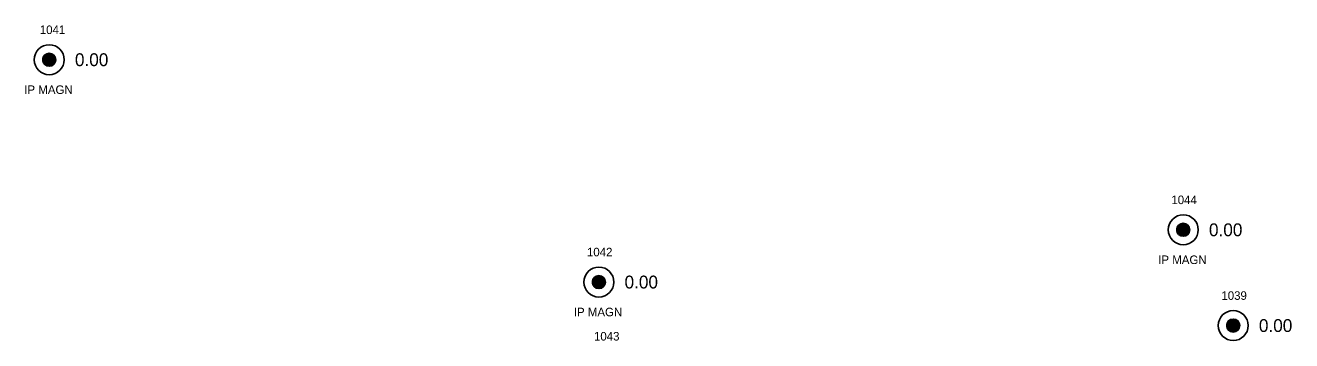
# Model space of a CAD drawing. Extents: x 1539151 to 1541799, y 1198646 to 1201165.
# Drawn here: x 1539955.6 to 1540103.4, y 1199874.2 to 1199911 of the extents above; entities that cross this region are included whole.
import ezdxf

# ---------------------------------------------------------------- set-up
doc = ezdxf.new("R2010")
doc.units = 0
for name, color, linetype in [('RD_EX_DV_Prop_txCode', 7, 'Continuous'), ('RD_EX_DV_PropPin', 7, 'Continuous'), ('RD_EX_TX_DV_Prop_ELEV', 7, 'Continuous'), ('RD_SMD_Locator', 7, 'Continuous')]:
    doc.layers.add(name, color=color, linetype=linetype)

msp = doc.modelspace()

# ---------------------------------------------------------------- linework, layer by layer
at = {"layer": 'RD_EX_DV_PropPin'}
for p, q in [((1539957.97, 1199906.34), (1539957.97, 1199907.66)), ((1539958.01, 1199906.32), (1539958.01, 1199907.67)), ((1539958.04, 1199906.31), (1539958.04, 1199907.69)), ((1539958.08, 1199906.29), (1539958.08, 1199907.71)), ((1539958.11, 1199906.28), (1539958.11, 1199907.72)), ((1539958.15, 1199906.27), (1539958.15, 1199907.73)), ((1539958.18, 1199906.26), (1539958.18, 1199907.74)), ((1539958.22, 1199906.25), (1539958.22, 1199907.75)), ((1539958.25, 1199906.25), (1539958.25, 1199907.75)), ((1539958.29, 1199906.24), (1539958.29, 1199907.76)), ((1539958.32, 1199906.24), (1539958.32, 1199907.76)), ((1539958.36, 1199906.24), (1539958.36, 1199907.76)), ((1539958.39, 1199906.24), (1539958.39, 1199907.76)), ((1539958.43, 1199906.24), (1539958.43, 1199907.76)), ((1539958.46, 1199906.25), (1539958.46, 1199907.75)), ((1539958.5, 1199906.25), (1539958.5, 1199907.75)), ((1539958.53, 1199906.26), (1539958.53, 1199907.74)), ((1539958.57, 1199906.27), (1539958.57, 1199907.73)), ((1539958.6, 1199906.28), (1539958.6, 1199907.72)), ((1539958.64, 1199906.29), (1539958.64, 1199907.71)), ((1539958.67, 1199906.31), (1539958.67, 1199907.69)), ((1539958.71, 1199906.32), (1539958.71, 1199907.67)), ((1539958.74, 1199906.34), (1539958.74, 1199907.66)), ((1539957.62, 1199906.8), (1539957.62, 1199907.2)), ((1539957.66, 1199906.7), (1539957.66, 1199907.3)), ((1539957.69, 1199906.63), (1539957.69, 1199907.37)), ((1539957.73, 1199906.57), (1539957.73, 1199907.43)), ((1539957.76, 1199906.53), (1539957.76, 1199907.47)), ((1539957.8, 1199906.48), (1539957.8, 1199907.51)), ((1539957.83, 1199906.45), (1539957.83, 1199907.55)), ((1539957.87, 1199906.42), (1539957.87, 1199907.58)), ((1539957.9, 1199906.39), (1539957.9, 1199907.61)), ((1539957.94, 1199906.36), (1539957.94, 1199907.63)), ((1539958.78, 1199906.36), (1539958.78, 1199907.63)), ((1539958.81, 1199906.39), (1539958.81, 1199907.61)), ((1539958.85, 1199906.42), (1539958.85, 1199907.58)), ((1539958.88, 1199906.45), (1539958.88, 1199907.55)), ((1539958.92, 1199906.48), (1539958.92, 1199907.51)), ((1539958.95, 1199906.53), (1539958.95, 1199907.47)), ((1539958.99, 1199906.57), (1539958.99, 1199907.43)), ((1539959.02, 1199906.63), (1539959.02, 1199907.37)), ((1539959.06, 1199906.7), (1539959.06, 1199907.3)), ((1539959.09, 1199906.8), (1539959.09, 1199907.2)), ((1540090.04, 1199886.94), (1540090.04, 1199887.33)), ((1540090.08, 1199886.84), (1540090.08, 1199887.44)), ((1540090.11, 1199886.77), (1540090.11, 1199887.51)), ((1540090.15, 1199886.71), (1540090.15, 1199887.56)), ((1540090.18, 1199886.66), (1540090.18, 1199887.61)), ((1540090.22, 1199886.62), (1540090.22, 1199887.65)), ((1540090.25, 1199886.59), (1540090.25, 1199887.69)), ((1540090.29, 1199886.56), (1540090.29, 1199887.72)), ((1540090.32, 1199886.53), (1540090.32, 1199887.75)), ((1540090.36, 1199886.5), (1540090.36, 1199887.77)), ((1540090.39, 1199886.48), (1540090.39, 1199887.79)), ((1540090.43, 1199886.46), (1540090.43, 1199887.81)), ((1540090.46, 1199886.45), (1540090.46, 1199887.83)), ((1540090.5, 1199886.43), (1540090.5, 1199887.85)), ((1540090.53, 1199886.42), (1540090.53, 1199887.86)), ((1540090.57, 1199886.41), (1540090.57, 1199887.87)), ((1540090.6, 1199886.4), (1540090.6, 1199887.88)), ((1540090.64, 1199886.39), (1540090.64, 1199887.89)), ((1540090.67, 1199886.38), (1540090.67, 1199887.89)), ((1540090.71, 1199886.38), (1540090.71, 1199887.9)), ((1540090.74, 1199886.38), (1540090.74, 1199887.9)), ((1540090.78, 1199886.38), (1540090.78, 1199887.9)), ((1540090.81, 1199886.38), (1540090.81, 1199887.9)), ((1540090.85, 1199886.38), (1540090.85, 1199887.9)), ((1540090.88, 1199886.38), (1540090.88, 1199887.89)), ((1540090.92, 1199886.39), (1540090.92, 1199887.89)), ((1540090.95, 1199886.4), (1540090.95, 1199887.88)), ((1540090.99, 1199886.41), (1540090.99, 1199887.87)), ((1540091.02, 1199886.42), (1540091.02, 1199887.86)), ((1540091.06, 1199886.43), (1540091.06, 1199887.85)), ((1540091.09, 1199886.45), (1540091.09, 1199887.83)), ((1540091.13, 1199886.46), (1540091.13, 1199887.81)), ((1540091.16, 1199886.48), (1540091.16, 1199887.79)), ((1540091.2, 1199886.5), (1540091.2, 1199887.77)), ((1540091.23, 1199886.53), (1540091.23, 1199887.75)), ((1540091.27, 1199886.56), (1540091.27, 1199887.72)), ((1540091.3, 1199886.59), (1540091.3, 1199887.69)), ((1540091.34, 1199886.62), (1540091.34, 1199887.65)), ((1540091.37, 1199886.66), (1540091.37, 1199887.61)), ((1540091.41, 1199886.71), (1540091.41, 1199887.56)), ((1540091.44, 1199886.77), (1540091.44, 1199887.51)), ((1540091.48, 1199886.84), (1540091.48, 1199887.44)), ((1540091.51, 1199886.94), (1540091.51, 1199887.33)), ((1540021.8, 1199880.84), (1540021.8, 1199881.24)), ((1540021.84, 1199880.74), (1540021.84, 1199881.34)), ((1540021.87, 1199880.67), (1540021.87, 1199881.41)), ((1540021.91, 1199880.61), (1540021.91, 1199881.47)), ((1540021.94, 1199880.56), (1540021.94, 1199881.51)), ((1540021.98, 1199880.52), (1540021.98, 1199881.55)), ((1540022.01, 1199880.49), (1540022.01, 1199881.59)), ((1540022.05, 1199880.46), (1540022.05, 1199881.62)), ((1540022.08, 1199880.43), (1540022.08, 1199881.65)), ((1540022.12, 1199880.4), (1540022.12, 1199881.67)), ((1540022.15, 1199880.38), (1540022.15, 1199881.7)), ((1540022.19, 1199880.36), (1540022.19, 1199881.71)), ((1540022.22, 1199880.35), (1540022.22, 1199881.73)), ((1540022.26, 1199880.33), (1540022.26, 1199881.75)), ((1540022.29, 1199880.32), (1540022.29, 1199881.76)), ((1540022.33, 1199880.31), (1540022.33, 1199881.77)), ((1540022.36, 1199880.3), (1540022.36, 1199881.78)), ((1540022.4, 1199880.29), (1540022.4, 1199881.79)), ((1540022.43, 1199880.29), (1540022.43, 1199881.79)), ((1540022.47, 1199880.28), (1540022.47, 1199881.8)), ((1540022.5, 1199880.28), (1540022.5, 1199881.8)), ((1540022.54, 1199880.28), (1540022.54, 1199881.8)), ((1540022.57, 1199880.28), (1540022.57, 1199881.8)), ((1540022.61, 1199880.28), (1540022.61, 1199881.8)), ((1540022.64, 1199880.29), (1540022.64, 1199881.79)), ((1540022.68, 1199880.29), (1540022.68, 1199881.79)), ((1540022.71, 1199880.3), (1540022.71, 1199881.78)), ((1540022.75, 1199880.31), (1540022.75, 1199881.77)), ((1540022.78, 1199880.32), (1540022.78, 1199881.76)), ((1540022.82, 1199880.33), (1540022.82, 1199881.75)), ((1540022.85, 1199880.35), (1540022.85, 1199881.73)), ((1540022.89, 1199880.36), (1540022.89, 1199881.71)), ((1540022.92, 1199880.38), (1540022.92, 1199881.7)), ((1540022.96, 1199880.4), (1540022.96, 1199881.67)), ((1540022.99, 1199880.43), (1540022.99, 1199881.65)), ((1540023.03, 1199880.46), (1540023.03, 1199881.62)), ((1540023.06, 1199880.49), (1540023.06, 1199881.59)), ((1540023.1, 1199880.52), (1540023.1, 1199881.55)), ((1540023.13, 1199880.56), (1540023.13, 1199881.51)), ((1540023.17, 1199880.61), (1540023.17, 1199881.47)), ((1540023.2, 1199880.67), (1540023.2, 1199881.41)), ((1540023.24, 1199880.74), (1540023.24, 1199881.34)), ((1540023.27, 1199880.84), (1540023.27, 1199881.24)), ((1540096.19, 1199875.33), (1540096.19, 1199876.6)), ((1540096.23, 1199875.31), (1540096.23, 1199876.62)), ((1540096.26, 1199875.29), (1540096.26, 1199876.64)), ((1540096.3, 1199875.27), (1540096.3, 1199876.66)), ((1540096.33, 1199875.26), (1540096.33, 1199876.67)), ((1540096.37, 1199875.24), (1540096.37, 1199876.68)), ((1540096.4, 1199875.23), (1540096.4, 1199876.7)), ((1540096.44, 1199875.22), (1540096.44, 1199876.7)), ((1540096.47, 1199875.22), (1540096.47, 1199876.71)), ((1540096.51, 1199875.21), (1540096.51, 1199876.72)), ((1540096.54, 1199875.21), (1540096.54, 1199876.72)), ((1540096.58, 1199875.2), (1540096.58, 1199876.72)), ((1540096.61, 1199875.2), (1540096.61, 1199876.72)), ((1540096.65, 1199875.2), (1540096.65, 1199876.72)), ((1540096.68, 1199875.21), (1540096.68, 1199876.72)), ((1540096.72, 1199875.21), (1540096.72, 1199876.72)), ((1540096.75, 1199875.22), (1540096.75, 1199876.71)), ((1540096.79, 1199875.22), (1540096.79, 1199876.7)), ((1540096.82, 1199875.23), (1540096.82, 1199876.7)), ((1540096.86, 1199875.24), (1540096.86, 1199876.68)), ((1540096.89, 1199875.26), (1540096.89, 1199876.67)), ((1540096.93, 1199875.27), (1540096.93, 1199876.66)), ((1540096.96, 1199875.29), (1540096.96, 1199876.64)), ((1540097, 1199875.31), (1540097, 1199876.62)), ((1540097.03, 1199875.33), (1540097.03, 1199876.6)), ((1540095.88, 1199875.77), (1540095.88, 1199876.16)), ((1540095.91, 1199875.67), (1540095.91, 1199876.26)), ((1540095.95, 1199875.59), (1540095.95, 1199876.33)), ((1540095.98, 1199875.54), (1540095.98, 1199876.39)), ((1540096.02, 1199875.49), (1540096.02, 1199876.44)), ((1540096.05, 1199875.45), (1540096.05, 1199876.48)), ((1540096.09, 1199875.41), (1540096.09, 1199876.51)), ((1540096.12, 1199875.38), (1540096.12, 1199876.55)), ((1540096.16, 1199875.35), (1540096.16, 1199876.57)), ((1540097.07, 1199875.35), (1540097.07, 1199876.57)), ((1540097.1, 1199875.38), (1540097.1, 1199876.55)), ((1540097.14, 1199875.41), (1540097.14, 1199876.51)), ((1540097.17, 1199875.45), (1540097.17, 1199876.48)), ((1540097.21, 1199875.49), (1540097.21, 1199876.44)), ((1540097.24, 1199875.54), (1540097.24, 1199876.39)), ((1540097.28, 1199875.59), (1540097.28, 1199876.33)), ((1540097.31, 1199875.67), (1540097.31, 1199876.26)), ((1540097.35, 1199875.77), (1540097.35, 1199876.16))]:
    msp.add_line(p, q, dxfattribs=at)
for centre, radius in [((1539958.36, 1199907), 1.75), ((1539958.36, 1199907), 0.761), ((1540090.78, 1199887.14), 1.75), ((1540090.78, 1199887.14), 0.761), ((1540022.54, 1199881.04), 1.75), ((1540022.54, 1199881.04), 0.761), ((1540096.61, 1199875.96), 1.75), ((1540096.61, 1199875.96), 0.761)]:
    msp.add_circle(centre, radius, dxfattribs=at)
at = {"layer": 'RD_SMD_Locator'}
for centre in [(1539958.36, 1199907), (1540090.78, 1199887.14), (1540022.54, 1199881.04), (1540096.61, 1199875.96)]:
    msp.add_circle(centre, 0.15, dxfattribs=at)

# ---------------------------------------------------------------- texts
at = {"layer": 'RD_EX_DV_Prop_txCode'}
for s, p in [('1041', (1539957.26, 1199910)), ('IP MAGN', (1539955.45, 1199903)), ('1044', (1540089.39, 1199890.14)), ('1042', (1540021.15, 1199884.04)), ('IP MAGN', (1540087.86, 1199883.14)), ('1039', (1540095.23, 1199878.96)), ('IP MAGN', (1540019.62, 1199877.04)), ('1043', (1540021.97, 1199874.21))]:
    msp.add_text(s, height=1, dxfattribs=at).set_placement(p)
at = {"layer": 'RD_EX_TX_DV_Prop_ELEV'}
for p in [(1539961.36, 1199906.25), (1540093.78, 1199886.39), (1540025.54, 1199880.29), (1540099.61, 1199875.21)]:
    msp.add_text('0.00', height=1.5, dxfattribs=at).set_placement(p)

doc.saveas('drawing.dxf')
